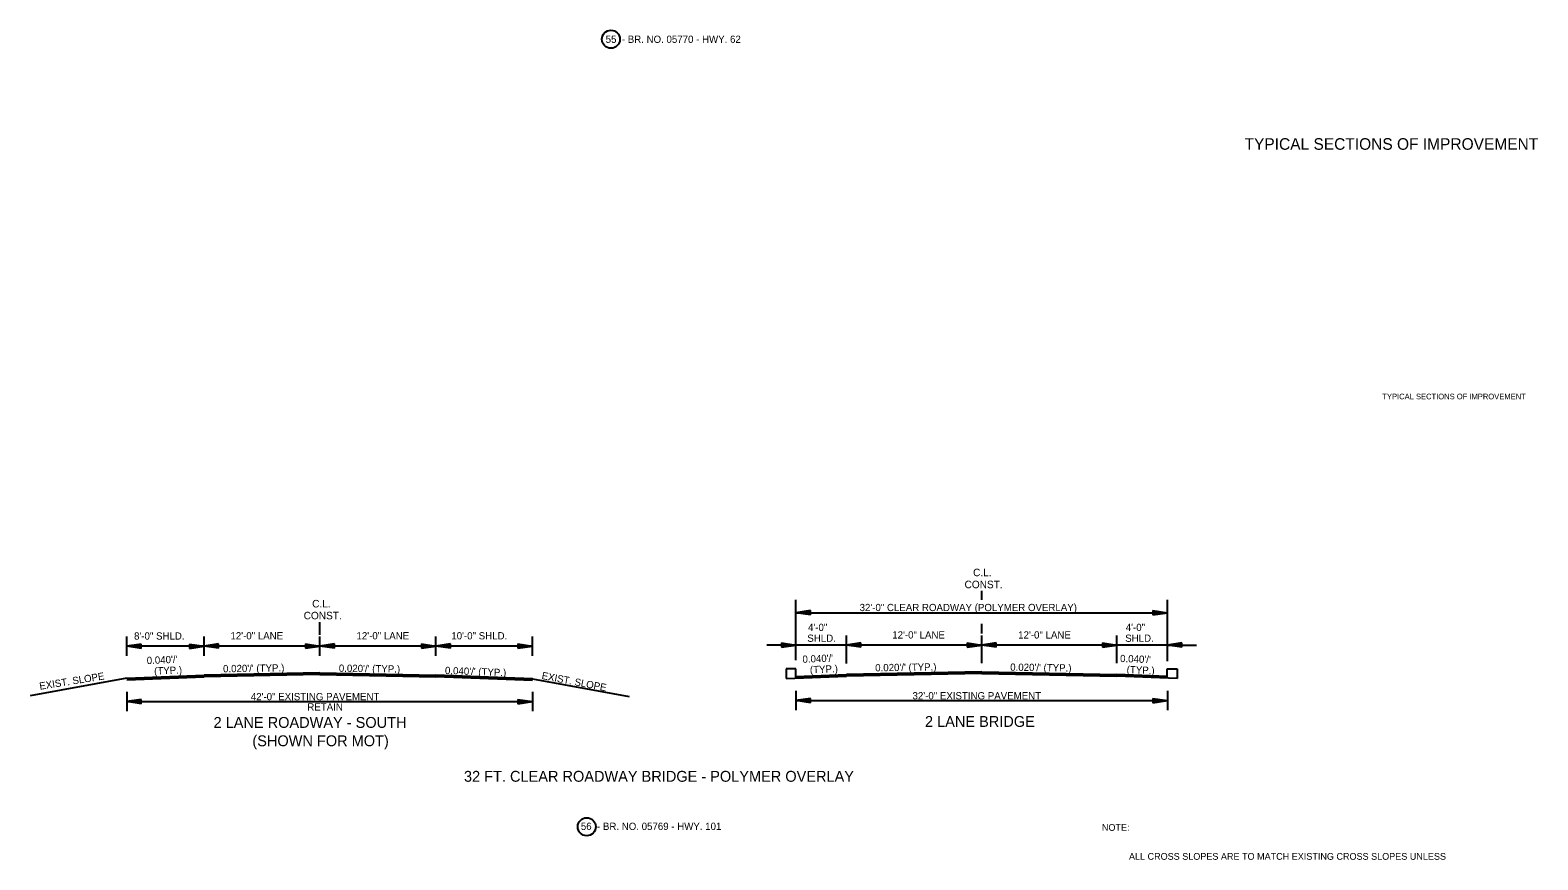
# Model space of a CAD drawing. Extents: x 550980 to 1930787, y -1972975 to 596640.
# Drawn here: x 550985 to 552546, y -1971211 to -1970351 of the extents above; entities that cross this region are included whole.
import ezdxf

# ---------------------------------------------------------------- set-up
doc = ezdxf.new("R2010")
doc.units = 0
for name, color, linetype in [('R_Border', 7, 'Continuous'), ('R_Border Notes', 7, 'Continuous'), ('R_Draft', 7, 'Continuous'), ('S_AREA_CALC', 7, 'Continuous')]:
    doc.layers.add(name, color=color, linetype=linetype)

msp = doc.modelspace()

# ---------------------------------------------------------------- linework, layer by layer
at = {"layer": 'R_Border'}
for p, q in [((551777.8, -1971012.8), (551767.6, -1971012.8)), ((551767.6, -1971012.8), (551767.6, -1971022.8)), ((551777.8, -1971022.2), (551777.8, -1971012.8)), ((552162.3, -1971022.2), (552162.3, -1971012.8)), ((552162.3, -1971012.8), (552172.5, -1971012.8)), ((552172.5, -1971012.8), (552172.5, -1971022.8))]:
    msp.add_line(p, q, dxfattribs=at)
for centre in [(551586.2, -1970360.8), (551561.2, -1971176.3)]:
    msp.add_circle(centre, 9.34, dxfattribs=at)
at = {"layer": 'R_Draft'}
for p, q in [((551970.1, -1970941.3), (551970.1, -1970932)), ((551777.8, -1971003.7), (551777.8, -1970941.3)), ((552162.4, -1971004.9), (552162.4, -1970941.3)), ((551792.8, -1970952.4), (551777.8, -1970954.7)), ((551777.8, -1970954.7), (552162.4, -1970954.7)), ((551792.8, -1970956.9), (551777.8, -1970954.7)), ((551792.8, -1970952.8), (551780.3, -1970954.7)), ((551792.8, -1970956.6), (551780.3, -1970954.7)), ((551792.8, -1970953.2), (551782.9, -1970954.7)), ((551792.8, -1970956.2), (551782.9, -1970954.7)), ((551792.8, -1970953.6), (551785.4, -1970954.7)), ((551792.8, -1970955.8), (551785.4, -1970954.7)), ((551792.8, -1970954), (551787.9, -1970954.7)), ((551792.8, -1970955.4), (551787.9, -1970954.7)), ((551792.8, -1970954.3), (551790.4, -1970954.7)), ((551792.8, -1970955), (551790.4, -1970954.7)), ((551792.8, -1970956.9), (551792.8, -1970952.4)), ((552147.4, -1970952.4), (552162.4, -1970954.7)), ((552147.4, -1970952.4), (552147.4, -1970956.9)), ((552147.4, -1970952.8), (552159.9, -1970954.7)), ((552147.4, -1970953.2), (552157.3, -1970954.7)), ((552147.4, -1970953.6), (552154.8, -1970954.7)), ((552147.4, -1970954), (552152.3, -1970954.7)), ((552147.4, -1970954.3), (552149.8, -1970954.7)), ((552147.4, -1970956.9), (552162.4, -1970954.7)), ((552147.4, -1970955.4), (552152.3, -1970954.7)), ((552147.4, -1970956.2), (552157.3, -1970954.7)), ((552147.4, -1970956.6), (552159.9, -1970954.7)), ((552147.4, -1970955.8), (552154.8, -1970954.7)), ((552147.4, -1970955), (552149.8, -1970954.7)), ((551285, -1970977.6), (551285, -1970964.4)), ((551830.1, -1971007.1), (551830.1, -1970978.3)), ((551970.1, -1970976.2), (551970.1, -1970966.3)), ((551970.1, -1971006.9), (551970.1, -1970978.3)), ((552110.1, -1971006.9), (552110.1, -1970978.3)), ((551085, -1970999.2), (551085, -1970979.2)), ((551100, -1970987.1), (551085, -1970989.3)), ((551165, -1970989.3), (551085, -1970989.3)), ((551100, -1970991.6), (551085, -1970989.3)), ((551100, -1970987.4), (551087.5, -1970989.3)), ((551100, -1970991.2), (551087.5, -1970989.3)), ((551100, -1970987.8), (551090.1, -1970989.3)), ((551100, -1970990.8), (551090.1, -1970989.3)), ((551100, -1970988.2), (551092.6, -1970989.3)), ((551100, -1970990.4), (551092.6, -1970989.3)), ((551100, -1970988.6), (551095.1, -1970989.3)), ((551100, -1970990.1), (551095.1, -1970989.3)), ((551100, -1970989), (551097.6, -1970989.3)), ((551100, -1970989.7), (551097.6, -1970989.3)), ((551100, -1970991.6), (551100, -1970987.1)), ((551150, -1970987.1), (551165, -1970989.3)), ((551150, -1970987.1), (551150, -1970991.6)), ((551150, -1970987.4), (551162.5, -1970989.3)), ((551150, -1970987.8), (551159.9, -1970989.3)), ((551150, -1970988.2), (551157.4, -1970989.3)), ((551150, -1970988.6), (551154.9, -1970989.3)), ((551150, -1970989), (551152.4, -1970989.3)), ((551150, -1970991.6), (551165, -1970989.3)), ((551150, -1970990.1), (551154.9, -1970989.3)), ((551150, -1970990.8), (551159.9, -1970989.3)), ((551150, -1970991.2), (551162.5, -1970989.3)), ((551150, -1970990.4), (551157.4, -1970989.3)), ((551150, -1970989.7), (551152.4, -1970989.3)), ((551165, -1970999.2), (551165, -1970979.3)), ((551180, -1970986.9), (551165, -1970989.2)), ((551285, -1970989.2), (551165, -1970989.2)), ((551180, -1970991.4), (551165, -1970989.2)), ((551180, -1970987.3), (551167.5, -1970989.2)), ((551180, -1970991), (551167.5, -1970989.2)), ((551180, -1970987.7), (551170.1, -1970989.2)), ((551180, -1970990.6), (551170.1, -1970989.2)), ((551180, -1970988), (551172.6, -1970989.2)), ((551180, -1970990.3), (551172.6, -1970989.2)), ((551180, -1970988.4), (551175.1, -1970989.2)), ((551180, -1970989.9), (551175.1, -1970989.2)), ((551180, -1970988.8), (551177.6, -1970989.2)), ((551180, -1970989.5), (551177.6, -1970989.2)), ((551180, -1970991.4), (551180, -1970986.9)), ((551270, -1970986.9), (551285, -1970989.2)), ((551270, -1970986.9), (551270, -1970991.4)), ((551270, -1970987.3), (551282.5, -1970989.2)), ((551270, -1970987.7), (551279.9, -1970989.2)), ((551270, -1970988), (551277.4, -1970989.2)), ((551270, -1970988.4), (551274.9, -1970989.2)), ((551270, -1970988.8), (551272.4, -1970989.2)), ((551270, -1970991.4), (551285, -1970989.2)), ((551270, -1970989.9), (551274.9, -1970989.2)), ((551270, -1970990.6), (551279.9, -1970989.2)), ((551270, -1970991), (551282.5, -1970989.2)), ((551270, -1970990.3), (551277.4, -1970989.2)), ((551270, -1970989.5), (551272.4, -1970989.2)), ((551285, -1970999.2), (551285, -1970979.3)), ((551300, -1970986.9), (551285, -1970989.2)), ((551405, -1970989.2), (551285, -1970989.2)), ((551300, -1970991.4), (551285, -1970989.2)), ((551300, -1970987.3), (551287.5, -1970989.2)), ((551300, -1970991), (551287.5, -1970989.2)), ((551300, -1970987.7), (551290.1, -1970989.2)), ((551300, -1970990.6), (551290.1, -1970989.2)), ((551300, -1970988), (551292.6, -1970989.2)), ((551300, -1970990.3), (551292.6, -1970989.2)), ((551300, -1970988.4), (551295.1, -1970989.2)), ((551300, -1970989.9), (551295.1, -1970989.2)), ((551300, -1970988.8), (551297.6, -1970989.2)), ((551300, -1970989.5), (551297.6, -1970989.2)), ((551300, -1970991.4), (551300, -1970986.9)), ((551390, -1970986.9), (551405, -1970989.2)), ((551390, -1970986.9), (551390, -1970991.4)), ((551390, -1970987.3), (551402.5, -1970989.2)), ((551390, -1970987.7), (551399.9, -1970989.2)), ((551390, -1970988), (551397.4, -1970989.2)), ((551390, -1970988.4), (551394.9, -1970989.2)), ((551390, -1970988.8), (551392.4, -1970989.2)), ((551390, -1970991.4), (551405, -1970989.2)), ((551390, -1970989.9), (551394.9, -1970989.2)), ((551390, -1970990.6), (551399.9, -1970989.2)), ((551390, -1970991), (551402.5, -1970989.2)), ((551390, -1970990.3), (551397.4, -1970989.2)), ((551390, -1970989.5), (551392.4, -1970989.2)), ((551405, -1970999.2), (551405, -1970979.3)), ((551420, -1970986.9), (551405, -1970989.2)), ((551420, -1970991.4), (551405, -1970989.2)), ((551505, -1970989.2), (551405, -1970989.2)), ((551420, -1970987.3), (551407.5, -1970989.2)), ((551420, -1970991), (551407.5, -1970989.2)), ((551420, -1970987.7), (551410.1, -1970989.2)), ((551420, -1970990.6), (551410.1, -1970989.2)), ((551420, -1970988), (551412.6, -1970989.2)), ((551420, -1970990.3), (551412.6, -1970989.2)), ((551420, -1970988.4), (551415.1, -1970989.2)), ((551420, -1970989.9), (551415.1, -1970989.2)), ((551420, -1970988.8), (551417.6, -1970989.2)), ((551420, -1970989.5), (551417.6, -1970989.2)), ((551420, -1970991.4), (551420, -1970986.9)), ((551490, -1970986.9), (551505, -1970989.2)), ((551490, -1970986.9), (551490, -1970991.4)), ((551490, -1970987.3), (551502.5, -1970989.2)), ((551490, -1970987.7), (551499.9, -1970989.2)), ((551490, -1970988), (551497.4, -1970989.2)), ((551490, -1970988.4), (551494.9, -1970989.2)), ((551490, -1970988.8), (551492.4, -1970989.2)), ((551490, -1970991.4), (551505, -1970989.2)), ((551490, -1970989.9), (551494.9, -1970989.2)), ((551490, -1970990.6), (551499.9, -1970989.2)), ((551490, -1970991), (551502.5, -1970989.2)), ((551490, -1970990.3), (551497.4, -1970989.2)), ((551490, -1970989.5), (551492.4, -1970989.2)), ((551505, -1970999.2), (551505, -1970979.2)), ((551777.8, -1970988.2), (551747.8, -1970988.2)), ((551762.8, -1970986), (551777.8, -1970988.2)), ((551762.8, -1970986), (551762.8, -1970990.5)), ((551762.8, -1970986.3), (551775.3, -1970988.2)), ((551762.8, -1970986.7), (551772.7, -1970988.2)), ((551762.8, -1970987.1), (551770.2, -1970988.2)), ((551762.8, -1970987.5), (551767.7, -1970988.2)), ((551762.8, -1970987.9), (551765.2, -1970988.2)), ((551762.8, -1970990.5), (551777.8, -1970988.2)), ((551762.8, -1970989), (551767.7, -1970988.2)), ((551762.8, -1970989.7), (551772.7, -1970988.2)), ((551762.8, -1970990.1), (551775.3, -1970988.2)), ((551762.8, -1970989.3), (551770.2, -1970988.2)), ((551762.8, -1970988.6), (551765.2, -1970988.2)), ((551830.1, -1970988.2), (551777.8, -1970988.2)), ((551845.1, -1970986), (551830.1, -1970988.2)), ((551970.1, -1970988.2), (551830.1, -1970988.2)), ((551845.1, -1970990.5), (551830.1, -1970988.2)), ((551845.1, -1970986.3), (551832.6, -1970988.2)), ((551845.1, -1970990.1), (551832.6, -1970988.2)), ((551845.1, -1970986.7), (551835.2, -1970988.2)), ((551845.1, -1970989.7), (551835.2, -1970988.2)), ((551845.1, -1970987.1), (551837.7, -1970988.2)), ((551845.1, -1970989.3), (551837.7, -1970988.2)), ((551845.1, -1970987.5), (551840.3, -1970988.2)), ((551845.1, -1970989), (551840.3, -1970988.2)), ((551845.1, -1970987.9), (551842.8, -1970988.2)), ((551845.1, -1970988.6), (551842.8, -1970988.2)), ((551845.1, -1970990.5), (551845.1, -1970986)), ((551955.1, -1970986), (551970.1, -1970988.2)), ((551955.1, -1970986), (551955.1, -1970990.5)), ((551955.1, -1970986.3), (551967.6, -1970988.2)), ((551955.1, -1970986.7), (551965, -1970988.2)), ((551955.1, -1970987.1), (551962.5, -1970988.2)), ((551955.1, -1970987.5), (551960, -1970988.2)), ((551955.1, -1970987.9), (551957.5, -1970988.2)), ((551955.1, -1970990.5), (551970.1, -1970988.2)), ((551955.1, -1970989), (551960, -1970988.2)), ((551955.1, -1970989.7), (551965, -1970988.2)), ((551955.1, -1970990.1), (551967.6, -1970988.2)), ((551955.1, -1970989.3), (551962.5, -1970988.2)), ((551955.1, -1970988.6), (551957.5, -1970988.2)), ((551985.1, -1970986), (551970.1, -1970988.2)), ((552110.1, -1970988.2), (551970.1, -1970988.2)), ((551985.1, -1970990.5), (551970.1, -1970988.2)), ((551985.1, -1970986.3), (551972.6, -1970988.2)), ((551985.1, -1970990.1), (551972.6, -1970988.2)), ((551985.1, -1970986.7), (551975.2, -1970988.2)), ((551985.1, -1970989.7), (551975.2, -1970988.2)), ((551985.1, -1970987.1), (551977.7, -1970988.2)), ((551985.1, -1970989.3), (551977.7, -1970988.2)), ((551985.1, -1970987.5), (551980.3, -1970988.2)), ((551985.1, -1970989), (551980.3, -1970988.2)), ((551985.1, -1970987.9), (551982.8, -1970988.2)), ((551985.1, -1970988.6), (551982.8, -1970988.2)), ((551985.1, -1970990.5), (551985.1, -1970986)), ((552095.1, -1970986), (552110.1, -1970988.2)), ((552095.1, -1970986), (552095.1, -1970990.5)), ((552095.1, -1970986.3), (552107.5, -1970988.2)), ((552095.1, -1970986.7), (552105, -1970988.2)), ((552095.1, -1970987.1), (552102.5, -1970988.2)), ((552095.1, -1970987.5), (552099.9, -1970988.2)), ((552095.1, -1970987.9), (552097.4, -1970988.2)), ((552095.1, -1970990.5), (552110.1, -1970988.2)), ((552095.1, -1970989), (552099.9, -1970988.2)), ((552095.1, -1970989.7), (552105, -1970988.2)), ((552095.1, -1970990.1), (552107.5, -1970988.2)), ((552095.1, -1970989.3), (552102.5, -1970988.2)), ((552095.1, -1970988.6), (552097.4, -1970988.2)), ((552162.4, -1970988.2), (552110.1, -1970988.2)), ((552177.4, -1970986), (552162.4, -1970988.2)), ((552177.4, -1970990.5), (552162.4, -1970988.2)), ((552162.4, -1970988.2), (552192.4, -1970988.2)), ((552177.4, -1970986.3), (552164.9, -1970988.2)), ((552177.4, -1970990.1), (552164.9, -1970988.2)), ((552177.4, -1970986.7), (552167.5, -1970988.2)), ((552177.4, -1970989.7), (552167.5, -1970988.2)), ((552177.4, -1970987.1), (552170, -1970988.2)), ((552177.4, -1970989.3), (552170, -1970988.2)), ((552177.4, -1970987.5), (552172.5, -1970988.2)), ((552177.4, -1970989), (552172.5, -1970988.2)), ((552177.4, -1970987.9), (552175, -1970988.2)), ((552177.4, -1970988.6), (552175, -1970988.2)), ((552177.4, -1970990.5), (552177.4, -1970986)), ((551085, -1971022.4), (550984.9, -1971040.7)), ((551085, -1971022.4), (551165, -1971019.2)), ((551085, -1971022.7), (551165, -1971019.5)), ((551085, -1971023), (551165, -1971019.8)), ((551085, -1971023.3), (551165, -1971020.1)), ((551085, -1971023.6), (551165, -1971020.4)), ((551085, -1971023.9), (551165, -1971020.7)), ((551085, -1971024.1), (551165, -1971020.9)), ((551285, -1971016.8), (551165, -1971019.2)), ((551285, -1971017.1), (551165, -1971019.5)), ((551285, -1971017.4), (551165, -1971019.8)), ((551285, -1971017.7), (551165, -1971020.1)), ((551285, -1971018), (551165, -1971020.4)), ((551285, -1971018.3), (551165, -1971020.7)), ((551285, -1971018.5), (551165, -1971020.9)), ((551285, -1971016.8), (551405, -1971019.2)), ((551285, -1971017.1), (551405, -1971019.5)), ((551285, -1971017.4), (551405, -1971019.8)), ((551285, -1971017.7), (551405, -1971020.1)), ((551285, -1971018), (551405, -1971020.4)), ((551285, -1971018.3), (551405, -1971020.7)), ((551285, -1971018.5), (551405, -1971020.9)), ((551505, -1971023.2), (551405, -1971019.2)), ((551505, -1971023.5), (551405, -1971019.5)), ((551505, -1971023.8), (551405, -1971019.8)), ((551505, -1971024.1), (551405, -1971020.1)), ((551505, -1971024.4), (551405, -1971020.4)), ((551505, -1971024.7), (551405, -1971020.7)), ((551505, -1971024.9), (551405, -1971020.9)), ((551505, -1971023.2), (551605.1, -1971041.5)), ((551767.6, -1971022.8), (551830.2, -1971020.3)), ((551777.8, -1971020.7), (551830.1, -1971018.6)), ((551777.8, -1971021), (551830.1, -1971018.9)), ((551777.8, -1971021.3), (551830.2, -1971019.2)), ((551777.8, -1971021.6), (551830.2, -1971019.5)), ((551777.8, -1971021.9), (551830.2, -1971019.8)), ((551777.8, -1971022.2), (551830.2, -1971020.1)), ((551970.1, -1971015.8), (551830.1, -1971018.6)), ((551970.1, -1971016.1), (551830.1, -1971018.9)), ((551970.1, -1971016.4), (551830.1, -1971019.2)), ((551970.1, -1971016.7), (551830.1, -1971019.5)), ((551970.2, -1971017), (551830.1, -1971019.8)), ((551970.2, -1971017.3), (551830.1, -1971020.1)), ((551970.2, -1971017.5), (551830.1, -1971020.3)), ((551970.1, -1971015.8), (552110.1, -1971018.6)), ((551970.1, -1971016.1), (552110.1, -1971018.9)), ((551970.1, -1971016.4), (552110.1, -1971019.2)), ((551970.1, -1971016.7), (552110.1, -1971019.5)), ((551970.1, -1971017), (552110.1, -1971019.8)), ((551970.1, -1971017.3), (552110.1, -1971020.1)), ((551970.1, -1971017.5), (552110.1, -1971020.3)), ((552162.3, -1971021), (552110, -1971018.9)), ((552162.3, -1971021.3), (552110, -1971019.2)), ((552162.3, -1971021.6), (552110, -1971019.5)), ((552162.3, -1971021.9), (552110, -1971019.8)), ((552162.3, -1971022.2), (552110, -1971020.1)), ((552172.5, -1971022.8), (552110, -1971020.3)), ((552162.3, -1971020.7), (552110.1, -1971018.6)), ((551085, -1971036.6), (551085, -1971056.6)), ((551505, -1971036.6), (551505, -1971056.6)), ((551777.8, -1971035.7), (551777.8, -1971055.7)), ((552162.4, -1971035.7), (552162.4, -1971055.7)), ((551100, -1971044.4), (551085, -1971046.6)), ((551085, -1971046.6), (551505, -1971046.6)), ((551100, -1971048.9), (551085, -1971046.6)), ((551100, -1971044.7), (551087.5, -1971046.6)), ((551100, -1971048.5), (551087.5, -1971046.6)), ((551100, -1971045.1), (551090.1, -1971046.6)), ((551100, -1971048.1), (551090.1, -1971046.6)), ((551100, -1971045.5), (551092.6, -1971046.6)), ((551100, -1971047.7), (551092.6, -1971046.6)), ((551100, -1971045.9), (551095.1, -1971046.6)), ((551100, -1971047.3), (551095.1, -1971046.6)), ((551100, -1971046.3), (551097.6, -1971046.6)), ((551100, -1971047), (551097.6, -1971046.6)), ((551100, -1971048.9), (551100, -1971044.4)), ((551490, -1971044.4), (551505, -1971046.6)), ((551490, -1971044.4), (551490, -1971048.9)), ((551490, -1971044.7), (551502.5, -1971046.6)), ((551490, -1971045.1), (551499.9, -1971046.6)), ((551490, -1971045.5), (551497.4, -1971046.6)), ((551490, -1971045.9), (551494.9, -1971046.6)), ((551490, -1971046.3), (551492.4, -1971046.6)), ((551490, -1971048.9), (551505, -1971046.6)), ((551490, -1971047.4), (551494.9, -1971046.6)), ((551490, -1971048.1), (551499.9, -1971046.6)), ((551490, -1971048.5), (551502.5, -1971046.6)), ((551490, -1971047.7), (551497.4, -1971046.6)), ((551490, -1971047), (551492.4, -1971046.6)), ((551792.8, -1971043.4), (551777.8, -1971045.7)), ((551777.8, -1971045.7), (552162.4, -1971045.7)), ((551792.8, -1971047.9), (551777.8, -1971045.7)), ((551792.8, -1971043.8), (551780.3, -1971045.7)), ((551792.8, -1971047.6), (551780.3, -1971045.7)), ((551792.8, -1971044.2), (551782.9, -1971045.7)), ((551792.8, -1971047.2), (551782.9, -1971045.7)), ((551792.8, -1971044.6), (551785.4, -1971045.7)), ((551792.8, -1971046.8), (551785.4, -1971045.7)), ((551792.8, -1971045), (551787.9, -1971045.7)), ((551792.8, -1971046.4), (551787.9, -1971045.7)), ((551792.8, -1971045.3), (551790.4, -1971045.7)), ((551792.8, -1971046), (551790.4, -1971045.7)), ((551792.8, -1971047.9), (551792.8, -1971043.4)), ((552147.4, -1971043.4), (552162.4, -1971045.7)), ((552147.4, -1971043.4), (552147.4, -1971047.9)), ((552147.4, -1971043.8), (552159.9, -1971045.7)), ((552147.4, -1971044.2), (552157.3, -1971045.7)), ((552147.4, -1971044.6), (552154.8, -1971045.7)), ((552147.4, -1971045), (552152.3, -1971045.7)), ((552147.4, -1971045.3), (552149.8, -1971045.7)), ((552147.4, -1971047.9), (552162.4, -1971045.7)), ((552147.4, -1971046.4), (552152.3, -1971045.7)), ((552147.4, -1971047.2), (552157.3, -1971045.7)), ((552147.4, -1971047.6), (552159.9, -1971045.7)), ((552147.4, -1971046.8), (552154.8, -1971045.7)), ((552147.4, -1971046), (552149.8, -1971045.7))]:
    msp.add_line(p, q, dxfattribs=at)

# ---------------------------------------------------------------- texts
at = {"layer": 'R_Border'}
msp.add_text('TYPICAL SECTIONS OF IMPROVEMENT', height=12, rotation=360, dxfattribs=at).set_placement((552242.3, -1970475.3))
msp.add_text('(SHOWN FOR MOT)', height=11.25, dxfattribs=at).set_placement((551215, -1971092.9))
at = {"layer": 'R_Border Notes'}
for s, p in [('NOTE: ', (552094.6, -1971180.5)), ('ALL CROSS SLOPES ARE TO MATCH EXISTING CROSS SLOPES UNLESS ', (552122.6, -1971210.5))]:
    msp.add_text(s, height=7, dxfattribs=at).set_placement(p)
at = {"layer": 'R_Draft'}
for s, height, p in [('55  - BR. NO. 05770 - HWY. 62', 7.5, (551580.8, -1970364.6)), ('C.L.', 7.8, (551961.2, -1970916.9)), ('CONST.', 7.8, (551952.4, -1970929.3)), ('C.L.', 7.8, (551276.9, -1970949.2)), ('32\'-0" CLEAR ROADWAY (POLYMER OVERLAY)', 7.5, (551843.7, -1970953)), ('CONST.', 7.8, (551268.1, -1970961.5)), ('8\'-0" SHLD.', 7.5, (551092.5, -1970982.5)), ('12\'-0" LANE', 7.5, (551192.3, -1970982.3)), ('12\'-0" LANE', 7.5, (551322.8, -1970982.3)), ('10\'-0" SHLD.', 7.5, (551421, -1970982.3)), ('SHLD.', 7.5, (551789.6, -1970984.8)), ('4\'-0" ', 7.5, (551790.3, -1970973.6)), ('12\'-0" LANE', 7.5, (551877.5, -1970981.4)), ('12\'-0" LANE', 7.5, (552007.9, -1970981.4)), ('SHLD.', 7.5, (552118.7, -1970984.8)), ('4\'-0" ', 7.5, (552119.3, -1970973.6)), ('42\'-0" EXISTING PAVEMENT', 7.5, (551213.4, -1971045.3)), ('32\'-0" EXISTING PAVEMENT', 7.5, (551898.5, -1971044.4)), ('RETAIN', 7.5, (551271.9, -1971056)), ('2 LANE ROADWAY - SOUTH', 11.25, (551174.8, -1971073.9)), ('2 LANE BRIDGE', 11.25, (551911.4, -1971072.9)), ('32 FT. CLEAR ROADWAY BRIDGE - POLYMER OVERLAY', 11.25, (551434.1, -1971129.7)), ('56  - BR. NO. 05769 - HWY. 101', 7.5, (551555.1, -1971179.6))]:
    msp.add_text(s, height=height, dxfattribs=at).set_placement(p)
for s, rotation, p in [("0.040'/' ", 2.448, (551105.8, -1971007.9)), ('(TYP.)', 2.448, (551113.4, -1971018.8)), ("0.020'/' (TYP.)", 0.8719, (551184.7, -1971016.4)), ("0.020'/' (TYP.)", 359.164, (551304.5, -1971015.8)), ("0.040'/' ", 2.448, (551784.7, -1971006.6)), ('(TYP.)', 2.448, (551792.4, -1971017.5)), ("0.020'/' (TYP.)", 0.8719, (551859.9, -1971015.4)), ("0.020'/' (TYP.)", 359.164, (551999.6, -1971014.7)), ("0.040'/'", 357.8168, (552113.3, -1971005.7)), ('(TYP.)', 357.8168, (552120.1, -1971017.2)), ('EXIST. SLOPE', 9.1534, (550995.1, -1971034.5)), ("0.040'/' (TYP.)", 357.8168, (551414.3, -1971018.1)), ('EXIST. SLOPE', 349.1171, (551514.1, -1971023.2))]:
    msp.add_text(s, height=7.5, rotation=rotation, dxfattribs=at).set_placement(p)
at = {"layer": 'S_AREA_CALC'}
msp.add_text('TYPICAL SECTIONS OF IMPROVEMENT', height=5.862, rotation=360, dxfattribs=at).set_placement((552384.9, -1970733.7))

doc.saveas('drawing.dxf')
